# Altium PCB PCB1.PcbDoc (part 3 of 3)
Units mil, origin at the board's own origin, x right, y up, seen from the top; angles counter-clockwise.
Board outline 3586 x 4364 mil, 2 copper layers (Top Layer, Bottom Layer); 0 components, 57 nets, 205 pads, 0 vias.
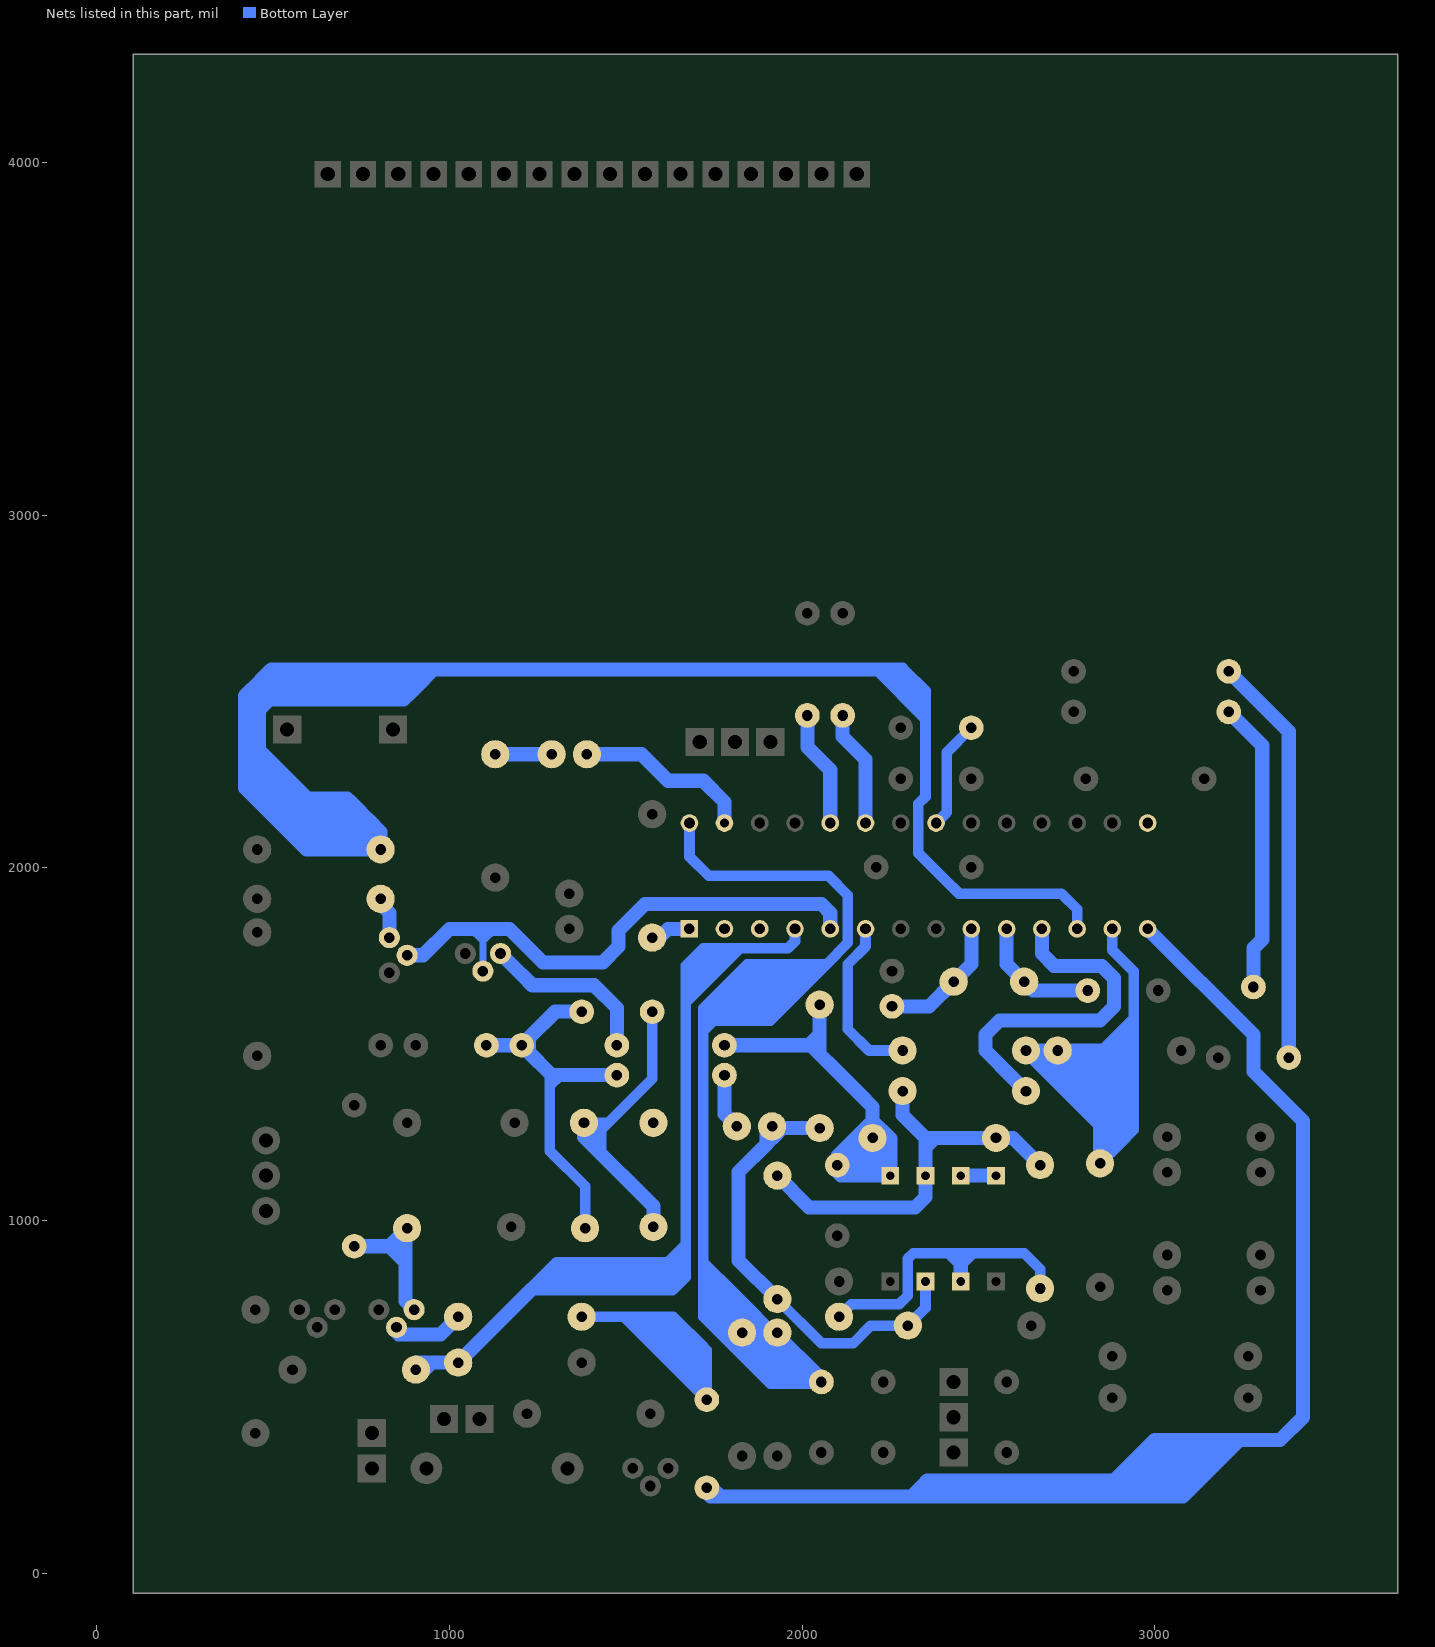
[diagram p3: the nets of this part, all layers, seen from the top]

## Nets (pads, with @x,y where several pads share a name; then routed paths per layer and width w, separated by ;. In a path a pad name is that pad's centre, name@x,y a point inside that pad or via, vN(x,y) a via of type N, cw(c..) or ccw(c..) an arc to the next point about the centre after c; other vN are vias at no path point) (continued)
$Net22: pad.1@904.35,576.74 pad.1@1024.35,596.74 pad.1@1979.35,1826.74 | length 5190.5
  Bottom Layer w30: pad.1@1024.35,596.74 1024.35,601.74 1154.35,731.74 1224.35,801.74 ; 1269.35,831.74 1499.35,831.74 ; 1284.35,856.74 1279.35,856.74 1236.85,814.24 ; 1524.35,856.74 1499.35,831.74 ; 1576.85,831.74 1499.35,831.74 ; 1599.35,861.74 1614.35,876.74 1669.35,931.74 ; 1654.35,826.74 1629.35,801.74 ; 1674.35,1686.74 1759.35,1771.74 ; pad.1@1979.35,1826.74 1979.35,1791.74 1959.35,1771.74 1824.35,1771.74 ; 1224.35,801.74 1229.35,801.74 1494.35,801.74 1539.35,801.74 1579.35,801.74 1589.35,801.74 1596.85,801.74 ; 1224.35,801.74 1236.85,814.24 ; 1236.85,814.24 1241.85,814.24 1481.85,814.24 ; 1481.85,814.24 1534.35,814.24 1566.85,814.24 ; 1481.85,814.24 1499.35,831.74 ; 1566.85,814.24 1579.35,814.24 1589.35,814.24 1599.35,814.24 ; 1566.85,814.24 1609.35,856.74 1629.35,876.74 1669.35,916.74 ; 1596.85,801.74 1619.35,801.74 1629.35,801.74 ; 1596.85,801.74 1609.35,814.24 ; 1599.35,814.24 1669.35,884.24 ; 1599.35,814.24 1609.35,814.24 ; 1609.35,814.24 1618.15,823.04 1669.35,874.24 ; 1629.35,801.74 1631.85,801.74 1659.35,829.24 1669.35,839.24 1669.35,841.74 1669.35,874.24 ; 1669.35,874.24 1669.35,876.74 1669.35,884.24 ; 1669.35,884.24 1669.35,891.74 1669.35,896.74 1669.35,916.74 ; 1669.35,916.74 1669.35,931.74 ; 1669.35,931.74 1669.35,946.74 1669.35,1616.74 ; 1669.35,1616.74 1669.35,1646.74 ; 1669.35,1616.74 1824.35,1771.74 ; 1669.35,1646.74 1669.35,1706.74 ; 1669.35,1646.74 1794.35,1771.74 ; 1669.35,1706.74 1669.35,1721.74 1719.35,1771.74 1734.35,1771.74 ; 1669.35,1706.74 1734.35,1771.74 ; 1734.35,1771.74 1759.35,1771.74 ; 1759.35,1771.74 1794.35,1771.74 ; 1794.35,1771.74 1824.35,1771.74
  Bottom Layer w40: pad.1@904.35,576.74 pad.1@924.35,596.74 ; pad.1@904.35,596.74 pad.1@924.35,596.74 ; pad.1@914.35,561.74 949.35,596.74 ; 1624.35,856.74 1609.35,856.74 1524.35,856.74 1364.35,856.74 1339.35,856.74 1284.35,856.74 ; 1644.35,876.74 1629.35,876.74 1614.35,876.74 1304.35,876.74 1284.35,856.74 ; pad.1@924.35,596.74 949.35,596.74 ; 949.35,596.74 974.35,596.74 pad.1@1024.35,596.74 1204.35,776.74 1229.35,801.74 1241.85,814.24 1284.35,856.74
$Net23: pad.1@1680.15,2126.74 pad.1@1829.35,681.74 pad.1@1929.35,681.74 pad.1@2054.35,541.74 | length 8401.9
  Bottom Layer w30: pad.1@1680.15,2126.74 1680.15,2031.04 1734.35,1976.74 2074.35,1976.74 2129.35,1921.74 2129.35,1786.74 2069.35,1726.74 ; 1724.35,741.74 1774.35,691.74 ; 1724.35,821.74 1796.85,749.24 ; 1729.35,746.74 1779.35,696.74 ; 1729.35,801.74 1789.35,741.74 ; 1729.35,846.74 1811.85,764.24 ; 1729.35,1571.74 1741.85,1584.24 ; 1794.35,1591.74 1849.35,1646.74 ; 1804.35,1581.74 1806.85,1584.24 ; pad.1@1809.35,681.74 pad.1@1829.35,681.74 ; pad.1@1819.35,666.74 pad.1@1839.35,646.74 ; 1819.35,756.74 1811.85,764.24 ; 1819.35,771.74 1811.85,764.24 ; 1824.35,641.74 1774.35,691.74 ; 1834.35,1576.74 1841.85,1584.24 ; pad.1@1839.35,706.74 pad.1@1839.35,681.74 ; 1844.35,631.74 1839.35,636.74 ; 1864.35,1581.74 1866.85,1584.24 ; 1874.35,646.74 1949.35,571.74 ; 1874.35,1716.74 1804.35,1646.74 ; 1894.35,1576.74 1901.85,1584.24 ; 1899.35,651.74 1979.35,571.74 ; pad.1@1899.35,661.74 1889.35,671.74 ; pad.1@1914.35,671.74 1889.35,671.74 ; 1919.35,1584.24 1901.85,1584.24 ; 1924.35,1721.74 1849.35,1646.74 ; pad.1@1932.45,668.74 pad.1@1930.85,670.34 ; 1944.35,1721.74 1869.35,1646.74 ; 1979.35,541.74 1949.35,571.74 ; 1979.35,1721.74 1904.35,1646.74 ; 1994.35,571.74 1979.35,571.74 ; 2004.35,1721.74 1929.35,1646.74 ; 2034.35,1716.74 1964.35,1646.74 ; pad.1@2049.35,536.74 pad.1@2039.35,536.74 ; pad.1@2049.35,561.74 pad.1@1929.35,681.74 ; 1719.35,791.74 1719.35,726.74 1764.35,681.74 ; 1719.35,791.74 1779.35,731.74 ; 1719.35,791.74 1719.35,831.74 1719.35,881.74 ; 1719.35,881.74 1809.35,791.74 1829.35,771.74 ; 1719.35,881.74 1719.35,916.74 1719.35,1536.74 ; 1719.35,1536.74 1719.35,1566.74 ; 1719.35,1536.74 1749.35,1566.74 ; 1719.35,1566.74 1719.35,1601.74 1764.35,1646.74 ; 1719.35,1566.74 1749.35,1566.74 ; 1741.85,1584.24 1804.35,1646.74 ; 1741.85,1584.24 1766.85,1584.24 ; 1749.35,1566.74 1864.35,1566.74 1904.35,1566.74 ; 1749.35,1566.74 1766.85,1584.24 ; 1764.35,681.74 1839.35,606.74 ; 1764.35,681.74 1774.35,691.74 ; 1764.35,1646.74 1779.35,1646.74 1804.35,1646.74 ; 1764.35,1646.74 1844.35,1726.74 1909.35,1726.74 ; 1766.85,1584.24 1829.35,1646.74 ; 1766.85,1584.24 1806.85,1584.24 ; 1774.35,691.74 1779.35,696.74 ; 1779.35,696.74 1839.35,636.74 ; 1779.35,696.74 1796.85,714.24 ; 1779.35,731.74 1796.85,714.24 ; 1779.35,731.74 1789.35,741.74 ; 1789.35,741.74 1806.85,724.24 ; 1789.35,741.74 1796.85,749.24 ; 1796.85,714.24 pad.1@1829.35,681.74 ; 1796.85,714.24 1806.85,724.24 ; 1796.85,749.24 1814.35,731.74 ; 1796.85,749.24 1811.85,764.24 ; 1804.35,1646.74 1829.35,1646.74 ; 1806.85,724.24 1809.35,721.74 pad.1@1829.35,681.74 ; 1806.85,724.24 1814.35,731.74 ; 1806.85,1584.24 1869.35,1646.74 ; 1806.85,1584.24 1841.85,1584.24 ; 1814.35,731.74 pad.1@1829.35,716.74 ; 1814.35,731.74 1829.35,746.74 ; pad.1@1829.35,681.74 pad.1@1829.35,716.74 ; pad.1@1829.35,681.74 pad.1@1839.35,681.74 ; pad.1@1829.35,681.74 pad.1@1839.35,679.24 ; pad.1@1829.35,681.74 pad.1@1839.35,671.74 ; pad.1@1829.35,716.74 1829.35,731.74 ; 1829.35,731.74 1829.35,746.74 ; 1829.35,731.74 1879.35,681.74 ; 1829.35,746.74 1829.35,771.74 ; 1829.35,771.74 pad.1@1919.35,681.74 ; 1829.35,1646.74 1909.35,1726.74 ; 1829.35,1646.74 1849.35,1646.74 ; 1839.35,606.74 1839.35,636.74 ; 1839.35,606.74 1889.35,556.74 1909.35,536.74 1949.35,536.74 ; 1839.35,636.74 pad.1@1839.35,646.74 ; pad.1@1839.35,646.74 1914.35,571.74 ; pad.1@1839.35,646.74 pad.1@1839.35,671.74 ; pad.1@1839.35,671.74 1914.35,596.74 1914.35,571.74 ; pad.1@1839.35,671.74 pad.1@1839.35,679.24 ; pad.1@1839.35,679.24 1869.35,671.74 1889.35,671.74 ; pad.1@1839.35,679.24 pad.1@1839.35,681.74 ; pad.1@1839.35,681.74 1879.35,681.74 ; 1841.85,1584.24 1904.35,1646.74 ; 1841.85,1584.24 1866.85,1584.24 ; 1849.35,1646.74 1869.35,1646.74 ; 1866.85,1584.24 1929.35,1646.74 ; 1866.85,1584.24 1901.85,1584.24 ; 1869.35,1646.74 1904.35,1646.74 ; 1879.35,681.74 pad.1@1914.35,681.74 ; 1879.35,681.74 1889.35,671.74 ; 1901.85,1584.24 1964.35,1646.74 ; 1904.35,1566.74 1984.35,1646.74 ; 1904.35,1566.74 1909.35,1566.74 2049.35,1706.74 2069.35,1726.74 ; 1904.35,1646.74 1929.35,1646.74 ; 1909.35,1726.74 1934.35,1726.74 1959.35,1726.74 2064.35,1726.74 ; 1914.35,571.74 1944.35,541.74 1949.35,536.74 ; 1914.35,571.74 1949.35,571.74 ; pad.1@1914.35,681.74 pad.1@1919.35,681.74 ; pad.1@1914.35,681.74 pad.1@1931.55,664.64 ; pad.1@1919.35,681.74 pad.1@1929.35,681.74 ; pad.1@1919.35,681.74 pad.1@1930.85,670.34 ; pad.1@1929.35,681.74 pad.1@1930.85,670.34 ; 1929.35,1646.74 1964.35,1646.74 ; pad.1@1930.85,670.34 pad.1@1931.55,664.64 ; pad.1@1931.55,664.64 2019.35,576.74 pad.1@2039.35,556.74 ; pad.1@1931.55,664.64 1934.35,641.74 2034.35,541.74 pad.1@2039.35,536.74 ; 1949.35,536.74 1979.35,536.74 2014.35,536.74 ; 1949.35,571.74 1979.35,571.74 ; 1964.35,1646.74 1984.35,1646.74 ; 1979.35,571.74 2009.35,541.74 2014.35,536.74 ; 1984.35,1646.74 2064.35,1726.74 ; 2014.35,536.74 pad.1@2039.35,536.74 ; pad.1@2039.35,556.74 pad.1@2054.35,541.74 2054.35,556.74 pad.1@2039.35,556.74 ; 2064.35,1726.74 2069.35,1726.74
  Bottom Layer w40: 1729.35,1596.74 1779.35,1646.74 1849.35,1716.74 ; 1959.35,541.74 1979.35,541.74 2009.35,541.74 2034.35,541.74 pad.1@2054.35,541.74
$Net24: pad.1@729.35,926.74 pad.1@879.35,977.74 pad.1@899.35,746.74 | length 518.6
  Bottom Layer w40: pad.1@729.35,926.74 829.35,926.74 ; 829.35,927.74 pad.1@874.35,972.74 ; 869.35,886.74 829.35,926.74 ; pad.1@899.35,746.74 874.35,771.74 874.35,796.74 874.35,826.74 874.35,841.74 874.35,926.74 ; 829.35,926.74 874.35,926.74 ; 874.35,926.74 pad.1@874.35,972.74 ; pad.1@874.35,972.74 874.35,977.74 pad.1@879.35,977.74 pad.1@874.35,972.74
$Net25: pad.1@1104.35,1496.74 pad.1@1204.35,1496.74 pad.1@1374.35,1591.74 pad.1@1384.15,977.74 pad.1@1474.35,1411.74 | length 1244.2
  Bottom Layer w30: 1284.35,1421.74 1284.35,1416.74 1284.35,1381.74 ; 1292.85,1407.24 1284.35,1381.74 ; 1314.35,1411.74 1284.35,1381.74 ; pad.1@1384.15,977.74 1384.15,1097.04 1284.35,1196.74 1284.35,1366.74 1284.35,1381.74
  Bottom Layer w40: pad.1@1104.35,1496.74 1169.35,1496.74 pad.1@1204.35,1496.74 ; pad.1@1374.35,1591.74 1354.35,1591.74 1319.35,1591.74 1299.35,1591.74 pad.1@1224.35,1516.74 ; pad.1@1474.35,1411.74 1359.35,1411.74 1334.35,1411.74 1314.35,1411.74 ; pad.1@1204.35,1496.74 pad.1@1224.35,1476.74 ; pad.1@1204.35,1496.74 pad.1@1224.35,1516.74 ; pad.1@1224.35,1476.74 1284.35,1416.74 1288.85,1411.74 ; pad.1@1224.35,1476.74 pad.1@1224.35,1516.74 ; 1288.85,1411.74 1292.85,1407.24 ; 1288.85,1411.74 1288.35,1411.74 1292.85,1407.24 ; 1288.85,1411.74 1314.35,1411.74 ; 1292.85,1407.24 1314.35,1411.74
$Net26: pad.1@1380.95,1276.74 pad.1@1574.35,1591.74 pad.1@1577.85,981.54 | length 953.9
  Bottom Layer w30: pad.1@1380.95,1276.74 1449.35,1276.74 ; 1394.35,1221.74 1395.15,1222.54 1429.35,1256.74 ; 1429.35,1192.54 1429.35,1256.74 ; pad.1@1574.35,1591.74 1574.35,1556.74 1574.35,1401.74 1456.85,1284.24 1449.35,1276.74 ; 1429.35,1256.74 1449.35,1276.74
  Bottom Layer w40: pad.1@1380.95,1276.74 1380.95,1236.74 1395.15,1222.54 1577.85,1039.94 pad.1@1577.85,981.54
$Net27: pad.1@1577.85,1276.74
$Net28: pad.1@849.35,696.74 pad.1@1024.35,726.74 | length 319
  Bottom Layer w30: pad.1@839.35,686.74 pad.1@854.35,671.74 ; pad.1@849.35,696.74 851.85,684.24 pad.1@854.35,671.74 ; 884.35,671.74 pad.1@854.35,671.74
  Bottom Layer w40: pad.1@1024.35,726.74 974.35,676.74 954.35,676.74 914.35,676.74 909.35,676.74 pad.1@869.35,676.74 ; pad.1@869.35,676.74 859.35,676.74 851.85,684.24 844.35,691.74 pad.1@849.35,696.74 pad.1@869.35,676.74
$Net29: pad.1@1374.35,726.74 pad.1@1729.35,491.74 | length 2055.6
  Bottom Layer w30: pad.1@1374.35,726.74 1494.35,726.74 ; 1524.35,716.74 1614.35,626.74 ; 1544.35,711.74 1629.35,626.74 ; 1569.35,706.74 1649.35,626.74 ; 1594.35,706.74 1674.35,626.74 ; 1609.35,626.74 1614.35,626.74 ; 1714.35,541.74 1629.35,626.74 ; 1719.35,581.74 1674.35,626.74 ; pad.1@1724.35,516.74 1614.35,626.74 ; 1724.35,551.74 1649.35,626.74 ; 1494.35,726.74 1559.35,726.74 1569.35,726.74 1609.35,726.74 ; 1494.35,726.74 pad.1@1729.35,491.74 1729.35,571.74 1729.35,606.74 ; 1609.35,726.74 1634.35,726.74 1644.35,716.74 1714.35,646.74 1729.35,631.74 1729.35,606.74 ; 1609.35,726.74 1709.35,626.74 ; 1614.35,626.74 1629.35,626.74 ; 1629.35,626.74 1649.35,626.74 ; 1649.35,626.74 1674.35,626.74 ; 1674.35,626.74 1709.35,626.74 ; 1709.35,626.74 1729.35,606.74
$Net30: pad.1@1914.35,1266.74 pad.1@1929.35,776.74 pad.1@2049.35,1261.74 pad.1@2299.35,701.74 pad.1@2349.35,826.74 | length 1438.3
  Bottom Layer w30: pad.1@1929.35,776.74 2054.35,651.74 2144.35,651.74 2194.35,701.74 pad.1@2299.35,701.74 2349.35,751.74 pad.1@2349.35,826.74
  Bottom Layer w40: pad.1@1899.35,1271.74 1899.35,1226.74 ; pad.1@1914.35,1261.74 pad.1@1919.35,1261.74 ; pad.1@1929.35,776.74 1819.35,886.74 1819.35,1136.74 1899.35,1216.74 ; pad.1@2049.35,1261.74 pad.1@1944.35,1261.74 ; 1899.35,1216.74 1904.35,1221.74 pad.1@1919.35,1236.74 ; 1899.35,1216.74 1899.35,1226.74 ; 1899.35,1226.74 pad.1@1914.35,1266.74 1919.35,1266.74 pad.1@1919.35,1261.74 ; pad.1@1919.35,1236.74 pad.1@1944.35,1261.74 ; pad.1@1919.35,1236.74 pad.1@1919.35,1261.74 ; pad.1@1919.35,1261.74 pad.1@1944.35,1261.74
$Net31: pad.1@1779.35,1496.74 pad.1@2049.35,1611.74 pad.1@2099.35,1156.74 pad.1@2199.35,1233.74 pad.1@2249.35,1126.74 | length 2460.8
  Bottom Layer w40: pad.1@1779.35,1496.74 2019.35,1496.74 ; pad.1@2049.35,1611.74 2049.35,1591.74 2049.35,1551.74 2049.35,1536.74 2049.35,1526.74 ; pad.1@2089.35,1166.74 pad.1@2099.35,1176.74 ; 2129.35,1206.74 2114.35,1191.74 ; 2169.35,1206.74 2176.55,1199.64 ; pad.1@2176.55,1209.64 pad.1@2199.35,1233.74 ; 2184.35,1146.74 2199.35,1161.74 ; 2184.35,1186.74 2194.35,1176.74 ; 2199.35,1146.74 2199.35,1161.74 ; 2239.35,1201.74 2206.85,1169.24 ; 2239.35,1221.74 2199.35,1181.74 ; 2239.35,1236.74 2199.35,1276.74 ; 2019.35,1496.74 2024.35,1496.74 ; 2019.35,1496.74 2049.35,1526.74 ; 2024.35,1496.74 2029.35,1496.74 2049.35,1496.74 ; 2024.35,1496.74 2049.35,1471.74 ; 2049.35,1471.74 2049.35,1496.74 ; 2049.35,1471.74 2089.35,1431.74 2154.35,1366.74 2164.35,1356.74 2199.35,1321.74 2199.35,1296.74 2199.35,1281.74 ; 2049.35,1496.74 2049.35,1506.74 2049.35,1526.74 ; pad.1@2099.35,1151.74 pad.1@2114.35,1136.74 ; pad.1@2099.35,1151.74 pad.1@2129.35,1151.74 ; pad.1@2099.35,1151.74 2099.35,1136.74 2109.35,1126.74 2124.35,1126.74 ; pad.1@2099.35,1151.74 pad.1@2099.35,1156.74 ; pad.1@2099.35,1156.74 pad.1@2099.35,1176.74 ; pad.1@2099.35,1156.74 pad.1@2104.35,1168.44 ; pad.1@2099.35,1156.74 pad.1@2104.35,1168.44 ; pad.1@2099.35,1156.74 pad.1@2104.35,1156.74 ; pad.1@2099.35,1176.74 pad.1@2104.35,1181.74 ; pad.1@2099.35,1176.74 2099.35,1181.74 pad.1@2104.35,1186.74 ; pad.1@2104.35,1156.74 2134.35,1156.74 ; pad.1@2104.35,1156.74 pad.1@2104.35,1168.44 ; pad.1@2104.35,1168.44 2114.35,1191.74 ; pad.1@2104.35,1168.44 2114.35,1191.74 ; pad.1@2104.35,1168.44 pad.1@2104.35,1181.74 ; pad.1@2104.35,1181.74 pad.1@2104.35,1186.74 ; pad.1@2104.35,1181.74 2114.35,1191.74 ; pad.1@2104.35,1186.74 2129.35,1211.74 2199.35,1281.74 ; pad.1@2114.35,1136.74 2124.35,1126.74 ; pad.1@2114.35,1136.74 pad.1@2129.35,1151.74 ; 2114.35,1191.74 2199.35,1276.74 ; 2124.35,1126.74 2144.35,1126.74 2174.35,1126.74 2179.35,1126.74 ; pad.1@2129.35,1151.74 2139.35,1151.74 ; pad.1@2129.35,1151.74 2134.35,1156.74 ; 2134.35,1156.74 2161.35,1183.74 2176.55,1199.64 ; 2134.35,1156.74 2139.35,1151.74 ; 2134.35,1156.74 2154.35,1156.74 ; 2139.35,1151.74 2149.35,1151.74 ; 2149.35,1151.74 2162.75,1151.74 ; 2149.35,1151.74 2154.35,1156.74 ; 2154.35,1156.74 2159.35,1156.74 2167.75,1156.74 2162.75,1151.74 ; 2162.75,1151.74 2169.35,1151.74 ; 2169.35,1151.74 2194.35,1176.74 ; 2169.35,1151.74 2179.35,1151.74 2179.35,1126.74 ; 2176.55,1199.64 2196.85,1179.24 ; 2179.35,1126.74 2219.35,1126.74 2244.35,1126.74 pad.1@2249.35,1126.74 ; 2194.35,1176.74 2199.35,1171.74 ; 2194.35,1176.74 2196.85,1179.24 ; 2196.85,1179.24 2199.35,1176.74 ; 2196.85,1179.24 2199.35,1181.74 ; 2199.35,1161.74 2204.35,1166.74 ; 2199.35,1161.74 2199.35,1171.74 ; 2199.35,1171.74 2204.35,1166.74 ; 2199.35,1171.74 2199.35,1176.74 ; 2199.35,1176.74 2206.85,1169.24 ; 2199.35,1176.74 2199.35,1181.74 ; 2199.35,1181.74 pad.1@2199.35,1233.74 ; pad.1@2199.35,1233.74 2199.35,1251.74 2199.35,1261.74 2199.35,1276.74 ; 2199.35,1276.74 2199.35,1281.74 ; 2199.35,1281.74 2249.35,1231.74 2249.35,1221.74 pad.1@2249.35,1126.74 ; 2204.35,1166.74 2224.35,1146.74 pad.1@2249.35,1126.74 ; 2204.35,1166.74 2206.85,1169.24 ; 2206.85,1169.24 2224.35,1151.74 2244.35,1131.74 pad.1@2249.35,1126.74
$Net32: pad.1@1929.35,1126.74 pad.1@2284.35,1366.74 pad.1@2349.35,1126.74 pad.1@2549.35,1233.74 pad.1@2674.35,1156.74 | length 1191.7
  Bottom Layer w40: pad.1@1929.35,1126.74 2019.35,1036.74 2059.35,1036.74 2159.35,1036.74 2319.35,1036.74 2349.35,1066.74 2349.35,1086.74 2349.35,1101.74 pad.1@2349.35,1126.74 2349.35,1206.74 ; pad.1@2284.35,1366.74 2284.35,1326.74 2284.35,1298.74 2349.35,1233.74 ; pad.1@2674.35,1156.74 2597.35,1233.74 2589.35,1233.74 pad.1@2549.35,1233.74 2509.35,1233.74 2444.35,1233.74 2376.35,1233.74 ; 2349.35,1206.74 2349.35,1233.74 ; 2349.35,1206.74 2376.35,1233.74 ; 2349.35,1233.74 2376.35,1233.74
$Net33: pad.1@2104.35,726.74 pad.1@2449.35,826.74 pad.1@2674.35,806.74 | length 1022.3
  Bottom Layer w30: pad.1@2104.35,726.74 2139.35,761.74 2274.35,761.74 2299.35,786.74 2299.35,891.74 2314.35,906.74 2414.35,906.74 ; 2449.35,901.74 2449.35,906.74 ; 2454.35,866.74 2449.35,871.74 ; pad.1@2674.35,806.74 2674.35,861.74 2629.35,906.74 2484.35,906.74 ; 2414.35,906.74 2429.35,891.74 2449.35,871.74 ; 2414.35,906.74 2429.35,906.74 ; 2429.35,906.74 2449.35,906.74 ; 2429.35,906.74 2449.35,886.74 2469.35,906.74 ; 2449.35,871.74 2464.35,886.74 2469.35,891.74 2484.35,906.74 ; 2449.35,906.74 2469.35,906.74 ; 2469.35,906.74 2474.35,906.74 2484.35,906.74
  Bottom Layer w40: pad.1@2449.35,826.74 2449.35,846.74 2449.35,871.74 2449.35,886.74 2449.35,896.74 2449.35,901.74
$Net34: pad.1@1574.35,1801.74 pad.1@1679.35,1826.74 | length 115.4
  Bottom Layer w40: pad.1@1574.35,1801.74 1594.35,1801.74 1619.35,1826.74 pad.1@1679.35,1826.74
$Net35: pad.1@804.35,2051.74 pad.1@2779.35,1826.74 | length 10549.6
  Bottom Layer w30: 414.35,2231.74 419.35,2226.74 ; 2209.35,2561.74 2349.35,2421.74 ; 2224.35,2561.74 2349.35,2436.74 ; 2254.35,2566.74 2284.35,2566.74 2289.35,2561.74 ; 2264.35,2556.74 2329.35,2491.74 2344.35,2476.74 2349.35,2471.74 ; 2279.35,2561.74 2289.35,2561.74 ; 2299.35,2546.74 2349.35,2496.74 ; 2349.35,2406.74 2349.35,2401.74 ; 2401.85,1969.24 2404.35,1966.74 ; pad.1@2779.35,1826.74 2779.35,1881.74 2734.35,1926.74 2639.35,1926.74 2629.35,1926.74 2589.35,1926.74 2584.35,1926.74 2549.35,1926.74 2509.35,1926.74 2454.35,1926.74 2444.35,1926.74 2404.35,1966.74 ; 2289.35,2561.74 2349.35,2501.74 2349.35,2496.74 ; 2349.35,2401.74 2349.35,2421.74 ; 2349.35,2401.74 2349.35,2201.74 2329.35,2181.74 2329.35,2041.74 2404.35,1966.74 ; 2349.35,2421.74 2349.35,2436.74 ; 2349.35,2436.74 2349.35,2471.74 ; 2349.35,2471.74 2349.35,2486.74 2349.35,2496.74
  Bottom Layer w40: 449.35,2206.74 449.35,2241.74 ; 454.35,2266.74 531.85,2189.24 ; 459.35,2296.74 459.35,2306.74 ; 519.35,2521.74 499.35,2501.74 ; 524.35,2146.74 544.35,2146.74 ; 534.35,2521.74 514.35,2501.74 ; 544.35,2121.74 569.35,2121.74 ; 569.35,2091.74 629.35,2091.74 ; 589.35,2101.74 569.35,2121.74 ; 604.35,2071.74 649.35,2071.74 ; 619.35,2106.74 604.35,2121.74 ; 624.35,2141.74 619.35,2146.74 ; 624.35,2156.74 614.35,2166.74 ; 729.35,2146.74 709.35,2146.74 ; 759.35,2121.74 734.35,2121.74 ; pad.1@774.35,2071.74 649.35,2071.74 ; 779.35,2091.74 764.35,2091.74 ; 876.85,2531.74 744.35,2531.74 ; 2319.35,2521.74 2279.35,2561.74 2239.35,2561.74 2224.35,2561.74 2209.35,2561.74 1124.35,2561.74 954.35,2561.74 ; 421.85,2224.24 419.35,2226.74 419.35,2251.74 419.35,2266.74 419.35,2436.74 419.35,2486.74 421.85,2489.24 ; 421.85,2224.24 434.35,2211.74 454.35,2191.74 479.35,2166.74 ; 421.85,2224.24 421.85,2236.74 421.85,2269.24 ; 421.85,2269.24 421.85,2406.74 421.85,2456.74 421.85,2489.24 ; 421.85,2269.24 449.35,2241.74 ; 421.85,2489.24 434.35,2501.74 449.35,2516.74 ; 449.35,2241.74 449.35,2276.74 ; 449.35,2241.74 524.35,2166.74 ; 449.35,2276.74 536.85,2189.24 ; 449.35,2276.74 449.35,2316.74 ; 449.35,2316.74 459.35,2306.74 ; 449.35,2316.74 449.35,2331.74 ; 449.35,2331.74 449.35,2344.24 ; 449.35,2331.74 459.35,2321.74 ; 449.35,2344.24 449.35,2436.74 ; 449.35,2344.24 459.35,2334.24 ; 449.35,2436.74 459.35,2446.74 ; 449.35,2436.74 449.35,2451.74 ; 449.35,2451.74 459.35,2461.74 ; 449.35,2451.74 449.35,2486.74 ; 449.35,2486.74 459.35,2486.74 484.35,2486.74 ; 449.35,2486.74 449.35,2501.74 ; 449.35,2501.74 499.35,2501.74 ; 449.35,2501.74 449.35,2516.74 ; 449.35,2516.74 459.35,2526.74 464.35,2531.74 ; 459.35,2306.74 576.85,2189.24 ; 459.35,2306.74 459.35,2321.74 ; 459.35,2321.74 584.35,2196.74 ; 459.35,2321.74 459.35,2334.24 ; 459.35,2334.24 596.85,2196.74 ; 459.35,2334.24 459.35,2446.74 ; 459.35,2446.74 489.35,2476.74 ; 459.35,2446.74 459.35,2461.74 ; 459.35,2461.74 474.35,2476.74 ; 459.35,2461.74 459.35,2476.74 474.35,2476.74 ; 464.35,2531.74 494.35,2561.74 569.35,2561.74 909.35,2561.74 ; 464.35,2531.74 714.35,2531.74 744.35,2531.74 ; 474.35,2476.74 484.35,2486.74 ; 474.35,2476.74 489.35,2476.74 ; 479.35,2166.74 504.35,2141.74 594.35,2051.74 669.35,2051.74 ; 479.35,2166.74 524.35,2166.74 ; 484.35,2486.74 499.35,2486.74 ; 484.35,2486.74 499.35,2501.74 ; 489.35,2476.74 499.35,2486.74 ; 489.35,2476.74 869.35,2476.74 879.35,2486.74 ; 499.35,2486.74 879.35,2486.74 ; 499.35,2486.74 514.35,2501.74 ; 499.35,2501.74 514.35,2501.74 ; 514.35,2501.74 714.35,2501.74 ; 524.35,2166.74 554.35,2166.74 ; 524.35,2166.74 544.35,2146.74 ; 531.85,2189.24 554.35,2166.74 ; 531.85,2189.24 536.85,2189.24 ; 536.85,2189.24 559.35,2166.74 ; 536.85,2189.24 576.85,2189.24 ; 544.35,2146.74 574.35,2146.74 ; 544.35,2146.74 569.35,2121.74 ; 554.35,2166.74 559.35,2166.74 ; 554.35,2166.74 559.35,2161.74 574.35,2146.74 ; 559.35,2166.74 599.35,2166.74 ; 559.35,2166.74 579.35,2146.74 ; 569.35,2121.74 599.35,2121.74 ; 574.35,2146.74 579.35,2146.74 ; 574.35,2146.74 599.35,2121.74 ; 576.85,2189.24 591.85,2189.24 ; 576.85,2189.24 599.35,2166.74 ; 579.35,2146.74 619.35,2146.74 ; 579.35,2146.74 604.35,2121.74 ; 584.35,2196.74 591.85,2189.24 ; 584.35,2196.74 596.85,2196.74 ; 591.85,2189.24 604.35,2189.24 ; 591.85,2189.24 614.35,2166.74 ; 596.85,2196.74 604.35,2189.24 ; 596.85,2196.74 709.35,2196.74 716.85,2189.24 ; 599.35,2121.74 604.35,2121.74 ; 599.35,2121.74 604.35,2116.74 629.35,2091.74 ; 599.35,2166.74 614.35,2166.74 ; 599.35,2166.74 619.35,2146.74 ; 604.35,2121.74 734.35,2121.74 ; 604.35,2189.24 716.85,2189.24 ; 614.35,2166.74 649.35,2166.74 684.35,2166.74 689.35,2166.74 ; 619.35,2146.74 709.35,2146.74 ; 629.35,2091.74 764.35,2091.74 ; 629.35,2091.74 649.35,2071.74 ; 649.35,2071.74 669.35,2051.74 ; 669.35,2051.74 pad.1@804.35,2051.74 ; 689.35,2166.74 739.35,2166.74 ; 689.35,2166.74 709.35,2146.74 ; 709.35,2146.74 734.35,2121.74 ; 714.35,2501.74 794.35,2501.74 849.35,2501.74 ; 714.35,2501.74 744.35,2531.74 ; 716.85,2189.24 739.35,2166.74 ; 734.35,2121.74 764.35,2091.74 ; 739.35,2166.74 761.85,2144.24 769.35,2136.74 804.35,2101.74 pad.1@804.35,2051.74 ; 764.35,2091.74 pad.1@804.35,2051.74 ; 849.35,2501.74 894.35,2501.74 ; 849.35,2501.74 909.35,2561.74 ; 879.35,2486.74 884.35,2491.74 894.35,2501.74 ; 894.35,2501.74 906.85,2514.24 954.35,2561.74 ; 909.35,2561.74 919.35,2561.74 954.35,2561.74
$Net36: pad.1@804.35,1911.74 pad.1@829.35,1801.74 | length 130.7
  Bottom Layer w40: pad.1@804.35,1911.74 794.35,1906.74 829.35,1871.74 pad.1@829.35,1801.74
$Net37: pad.1@2634.35,1481.74 pad.1@2724.35,1481.74 pad.1@2844.35,1161.74 pad.1@2879.35,1826.74 | length 4398.4
  Bottom Layer w30: pad.1@2724.35,1481.74 2769.35,1481.74 ; 2786.85,1419.24 2794.35,1426.74 2814.35,1446.74 ; 2809.35,1451.74 2814.35,1446.74 ; 2824.35,1441.74 2834.35,1451.74 2839.35,1456.74 2849.35,1466.74 2864.35,1481.74 2939.35,1556.74 ; pad.1@2844.35,1161.74 2899.35,1216.74 ; 2844.35,1316.74 2874.35,1316.74 ; 2844.35,1416.74 2814.35,1446.74 ; 2844.35,1451.74 2849.35,1451.74 2854.35,1456.74 2864.35,1466.74 2879.35,1481.74 2911.85,1514.24 ; 2874.35,1206.74 2874.35,1316.74 ; 2874.35,1471.74 2874.35,1466.74 2874.35,1456.74 ; pad.1@2879.35,1826.74 2879.35,1766.74 2939.35,1706.74 2939.35,1581.74 2939.35,1571.74 ; 2899.35,1499.24 2899.35,1481.74 2899.35,1456.74 ; 2904.35,1456.74 2899.35,1456.74 ; 2911.85,1239.24 2911.85,1309.24 2911.85,1316.74 ; 2924.35,1316.74 2911.85,1316.74 ; 2814.35,1446.74 2819.35,1451.74 2824.35,1456.74 2834.35,1466.74 2849.35,1481.74 2939.35,1571.74 ; 2874.35,1316.74 2874.35,1346.74 2874.35,1456.74 ; 2874.35,1316.74 2899.35,1316.74 ; 2874.35,1456.74 2899.35,1456.74 ; 2899.35,1216.74 2899.35,1291.74 2899.35,1316.74 ; 2899.35,1216.74 2939.35,1256.74 2939.35,1276.74 2939.35,1386.74 2939.35,1541.74 ; 2899.35,1316.74 2899.35,1321.74 2899.35,1456.74 ; 2899.35,1316.74 2904.35,1316.74 2911.85,1316.74 ; 2911.85,1316.74 2911.85,1481.74 2911.85,1514.24 ; 2911.85,1514.24 2939.35,1541.74 ; 2939.35,1541.74 2939.35,1556.74 ; 2939.35,1556.74 2939.35,1571.74
  Bottom Layer w40: pad.1@2619.35,1481.74 pad.1@2634.35,1481.74 ; pad.1@2640.05,1481.04 pad.1@2634.35,1481.74 ; 2679.35,1456.74 pad.1@2724.35,1456.74 ; 2724.35,1406.74 pad.1@2724.35,1456.74 ; 2749.35,1441.74 pad.1@2739.95,1456.74 ; 2764.35,1426.74 2779.35,1411.74 ; 2789.35,1431.74 2794.35,1426.74 2809.35,1411.74 ; 2809.35,1451.74 2819.35,1451.74 2834.35,1451.74 2844.35,1451.74 2844.35,1416.74 2844.35,1411.74 ; 2809.35,1481.74 pad.1@2724.35,1481.74 ; 2834.35,1466.74 2849.35,1466.74 2864.35,1466.74 2874.35,1466.74 2889.35,1466.74 ; pad.1@2844.35,1161.74 2844.35,1236.74 ; 2854.35,1236.74 2844.35,1246.74 ; 2864.35,1216.74 2844.35,1236.74 ; 2864.35,1251.74 2844.35,1271.74 ; 2869.35,1291.74 2844.35,1316.74 ; 2874.35,1456.74 2854.35,1456.74 2839.35,1456.74 2824.35,1456.74 2819.35,1456.74 2764.35,1456.74 ; 2899.35,1291.74 2874.35,1316.74 2844.35,1346.74 ; 2911.85,1309.24 2904.35,1316.74 2899.35,1321.74 2874.35,1346.74 2844.35,1376.74 ; 2919.35,1481.74 2911.85,1481.74 2899.35,1481.74 2879.35,1481.74 2864.35,1481.74 2849.35,1481.74 pad.1@2724.35,1481.74 ; pad.1@2634.35,1481.74 2844.35,1271.74 ; pad.1@2634.35,1481.74 2639.35,1481.74 pad.1@2724.35,1481.74 ; pad.1@2724.35,1456.74 pad.1@2724.35,1481.74 ; pad.1@2724.35,1456.74 pad.1@2739.95,1456.74 ; pad.1@2724.35,1481.74 pad.1@2739.95,1456.74 ; pad.1@2724.35,1481.74 2764.35,1456.74 ; pad.1@2739.95,1456.74 2764.35,1456.74 ; 2779.35,1411.74 2844.35,1346.74 ; 2779.35,1411.74 2809.35,1411.74 ; 2779.35,1411.74 2749.35,1411.74 2844.35,1316.74 ; 2809.35,1411.74 2844.35,1376.74 ; 2809.35,1411.74 2844.35,1411.74 ; 2844.35,1236.74 2844.35,1246.74 ; 2844.35,1246.74 2844.35,1266.74 2844.35,1271.74 ; 2844.35,1271.74 2844.35,1316.74 ; 2844.35,1316.74 2844.35,1346.74 ; 2844.35,1346.74 2844.35,1376.74 ; 2844.35,1376.74 2844.35,1411.74
$Net38: pad.1@2179.35,1826.74 pad.1@2284.35,1481.74 | length 485.6
  Bottom Layer w30: pad.1@2179.35,1826.74 2179.35,1776.74 2129.35,1726.74 2129.35,1541.74 2189.35,1481.74 pad.1@2284.35,1481.74
$Net39: pad.1@1389.35,2321.74 pad.1@1779.35,2126.74 | length 510.9
  Bottom Layer w40: pad.1@1384.35,2321.74 pad.1@1389.35,2321.74 1544.35,2321.74 1619.35,2246.74 1719.35,2246.74 1779.35,2186.74 pad.1@1779.35,2126.74
$Net40: pad.1@1129.35,2321.74 pad.1@1289.35,2321.74 | length 160
  Bottom Layer w40: pad.1@1129.35,2321.74 1284.35,2321.74 pad.1@1289.35,2321.74
$Net41: pad.1@2379.35,2126.74 pad.1@2479.35,2396.74 | length 311.4
  Bottom Layer w30: pad.1@2379.35,2126.74 2409.35,2156.74 2409.35,2276.74 2409.35,2306.74 2409.35,2326.74 pad.1@2479.35,2396.74
$Net42: pad.1@2254.35,1606.74 pad.1@2429.35,1676.74 pad.1@2479.35,1826.74 | length 374.7
  Bottom Layer w40: pad.1@2254.35,1606.74 2269.35,1606.74 2314.35,1606.74 2359.35,1606.74 pad.1@2429.35,1676.74 2479.35,1726.74 pad.1@2479.35,1826.74
$Net43: pad.1@2579.35,1826.74 pad.1@2629.35,1676.74 pad.1@2809.35,1651.74 | length 361.1
  Bottom Layer w40: pad.1@2579.35,1826.74 2579.35,1726.74 pad.1@2629.35,1676.74 2654.35,1651.74 2699.35,1651.74 2794.35,1651.74 pad.1@2809.35,1651.74
$Net44: pad.1@879.35,1751.74 pad.1@1094.35,1706.74 pad.1@2079.35,1826.74 | length 1653.6
  Bottom Layer w20: 1054.35,1831.74 1059.35,1826.74 1094.35,1791.74 ; pad.1@1094.35,1706.74 1094.35,1791.74 ; 1094.35,1826.74 1094.35,1791.74 ; 1134.35,1831.74 1129.35,1826.74 1094.35,1791.74
  Bottom Layer w40: pad.1@879.35,1751.74 894.35,1751.74 924.35,1751.74 999.35,1826.74 1059.35,1826.74 1094.35,1826.74 1104.35,1826.74 1129.35,1826.74 1169.35,1826.74 1264.35,1731.74 1434.35,1731.74 1479.35,1776.74 1479.35,1821.74 1554.35,1896.74 2054.35,1896.74 2079.35,1871.74 pad.1@2079.35,1826.74
$Net45: pad.1@1144.35,1756.74 pad.1@1474.35,1496.74 | length 499.2
  Bottom Layer w40: pad.1@1144.35,1756.74 1199.35,1701.74 1204.35,1696.74 1234.35,1666.74 1239.35,1666.74 1264.35,1666.74 1409.35,1666.74 1474.35,1601.74 pad.1@1474.35,1496.74
$Net46: pad.1@3209.35,2556.74 pad.1@3379.35,1461.74 | length 1165.4
  Bottom Layer w40: pad.1@3209.35,2556.74 3379.35,2386.74 3379.35,2041.74 3379.35,1981.74 3379.35,1756.74 3379.35,1641.74 pad.1@3379.35,1461.74
$Net47: pad.1@3209.35,2441.74 pad.1@3279.35,1661.74 | length 829.7
  Bottom Layer w40: pad.1@3209.35,2441.74 3304.35,2346.74 3304.35,2266.74 3304.35,2191.74 3304.35,1966.74 3304.35,1956.74 3304.35,1941.74 3304.35,1796.74 3279.35,1771.74 pad.1@3279.35,1661.74
$Net48: pad.1@1729.35,241.74 pad.1@2979.35,1826.74 | length 7053.6
  Bottom Layer w30: pad.1@1724.35,241.74 pad.1@1729.35,241.74 ; pad.1@1729.35,241.74 pad.1@1734.35,236.74 ; pad.1@1729.35,241.74 pad.1@1734.35,236.74 ; pad.1@1734.35,236.74 1739.35,231.74 pad.1@1734.35,236.74
  Bottom Layer w40: pad.1@1719.35,236.74 1739.35,216.74 pad.1@1749.35,216.74 ; pad.1@1724.35,241.74 1739.35,226.74 pad.1@1749.35,216.74 ; pad.1@1729.35,241.74 1764.35,221.74 ; pad.1@1739.35,231.74 1754.35,216.74 ; pad.1@1739.35,246.74 1764.35,221.74 ; 2829.35,221.74 2711.85,221.74 ; 2884.35,226.74 2919.35,261.74 ; 2924.35,221.74 2964.35,261.74 ; 2964.35,226.74 2999.35,261.74 ; pad.1@2979.35,1826.74 3279.35,1526.74 3279.35,1421.74 3419.35,1281.74 3419.35,441.74 3354.35,376.74 3239.35,376.74 ; 3029.35,326.74 3024.35,321.74 ; 3029.35,371.74 2991.85,334.24 2979.35,321.74 ; 3034.35,261.74 2999.35,261.74 ; 3039.35,221.74 3139.35,321.74 ; 3059.35,366.74 3014.35,321.74 ; 3064.35,326.74 3059.35,321.74 ; 3089.35,356.74 3054.35,321.74 ; 3104.35,326.74 3099.35,321.74 ; 3134.35,366.74 3089.35,321.74 ; 3164.35,346.74 3139.35,321.74 ; 3174.35,366.74 3129.35,321.74 ; pad.1@1749.35,216.74 1754.35,216.74 ; 1754.35,216.74 1759.35,216.74 1764.35,216.74 1769.35,216.74 ; 1764.35,221.74 1769.35,216.74 ; 1769.35,216.74 2234.35,216.74 2249.35,216.74 2269.35,216.74 2309.35,216.74 ; 2309.35,216.74 2341.85,249.24 ; 2309.35,216.74 2389.35,216.74 2449.35,216.74 2499.35,216.74 2724.35,216.74 2759.35,216.74 2764.35,216.74 2814.35,216.74 2964.35,216.74 2994.35,216.74 ; 2341.85,249.24 2374.35,249.24 2481.85,249.24 ; 2341.85,249.24 2354.35,261.74 2884.35,261.74 ; 2481.85,249.24 2454.35,221.74 2479.35,221.74 2494.35,221.74 2711.85,221.74 ; 2481.85,249.24 2504.35,249.24 2739.35,249.24 ; 2711.85,221.74 2739.35,249.24 ; 2739.35,249.24 2871.85,249.24 2884.35,261.74 ; 2884.35,261.74 2944.35,321.74 ; 2884.35,261.74 2919.35,261.74 ; 2919.35,261.74 2979.35,321.74 ; 2919.35,261.74 2964.35,261.74 ; 2944.35,321.74 2999.35,376.74 3219.35,376.74 ; 2944.35,321.74 2979.35,321.74 ; 2964.35,261.74 3024.35,321.74 ; 2964.35,261.74 2999.35,261.74 ; 2979.35,321.74 3014.35,321.74 ; 2994.35,216.74 3054.35,216.74 3079.35,216.74 3084.35,221.74 3089.35,226.74 3239.35,376.74 ; 2994.35,216.74 3099.35,321.74 ; 2999.35,261.74 3059.35,321.74 ; 3014.35,321.74 3024.35,321.74 ; 3024.35,321.74 3054.35,321.74 ; 3054.35,321.74 3059.35,321.74 ; 3059.35,321.74 3089.35,321.74 ; 3089.35,321.74 3099.35,321.74 ; 3099.35,321.74 3129.35,321.74 ; 3129.35,321.74 3139.35,321.74 ; 3139.35,321.74 3164.35,321.74 3219.35,376.74 ; 3219.35,376.74 3239.35,376.74
$Net49: pad.1@1779.35,1411.74 pad.1@1814.35,1266.74 | length 159.5
  Bottom Layer w40: pad.1@1779.35,1411.74 1779.35,1376.74 1779.35,1301.74 pad.1@1814.35,1266.74
$Net50: pad.1@2114.35,2431.74 pad.1@2179.35,2126.74 | length 331.9
  Bottom Layer w40: pad.1@2114.35,2431.74 2114.35,2371.74 2179.35,2306.74 2179.35,2151.74 pad.1@2179.35,2126.74
$Net51: pad.1@2014.35,2431.74 pad.1@2079.35,2126.74 | length 331.9
  Bottom Layer w40: pad.1@2014.35,2431.74 2014.35,2341.74 2079.35,2276.74 pad.1@2079.35,2126.74
$Net52: pad.1@1779.35,1826.74
$Net53: pad.1@1879.35,1826.74
$Net54: pad.1@2634.35,1366.74 pad.1@2679.35,1826.74 | length 991.2
  Bottom Layer w40: pad.1@2635.35,1365.74 pad.1@2634.35,1366.74 2599.35,1401.74 2519.35,1481.74 2519.35,1526.74 2559.35,1566.74 2844.35,1566.74 2884.35,1606.74 2884.35,1686.74 2849.35,1721.74 2714.35,1721.74 2679.35,1756.74 pad.1@2679.35,1826.74
$Net55: pad.1@2979.35,2126.74
$Net56: pad.1@2449.35,1126.74 pad.1@2549.35,1126.74 | length 100
  Bottom Layer w40: pad.1@2449.35,1126.74 pad.1@2549.35,1126.74
copper on no net: | length 3723.2
  Bottom Layer w23: 3005.45,3768.84 3117.95,3654.84 ; 3061.75,3711.84 3117.95,3768.84 ; 3267.95,3711.84 3174.25,3711.84 ; 3174.25,3711.84 3155.45,3692.84 3155.45,3673.84 3174.25,3654.84 3267.95,3654.84 3267.95,3768.84 3174.25,3768.84 3155.45,3749.84 3155.45,3730.84 3174.25,3711.84
  Bottom Layer w50: 3164.35,3336.74 2772.95,3761.84 2777.95,3301.84 2392.95,3761.84 2392.95,3376.84 2557.95,3211.84 3152.95,3211.84 3217.95,3276.84

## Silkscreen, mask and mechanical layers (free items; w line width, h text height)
Top Overlay:
  drawing of 2859 lines, arcs and shapes, not listed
